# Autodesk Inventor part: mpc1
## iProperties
Shininess: 64.0
Length Units: 11269
Angle Units: 11279
Time Units: 11290
Mass Units: 11283
Length Display Precision: 3
Angle Display Precision: 2
Compacted: True
Part Number: mpc1
Document SubType Name: Modeling
Created: 2004-07
Designer: Peter
Manufacturer: Standard
Standards Organization: Custom
Density: 0.0
Volumn: 0.0
Area: 0.0
PropertySet Name: Model Information
Control State: 0
Master: False
Checked Out: False
Author: Peter
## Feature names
1. Extrusion1
2. Fillet1
3. Hole1
